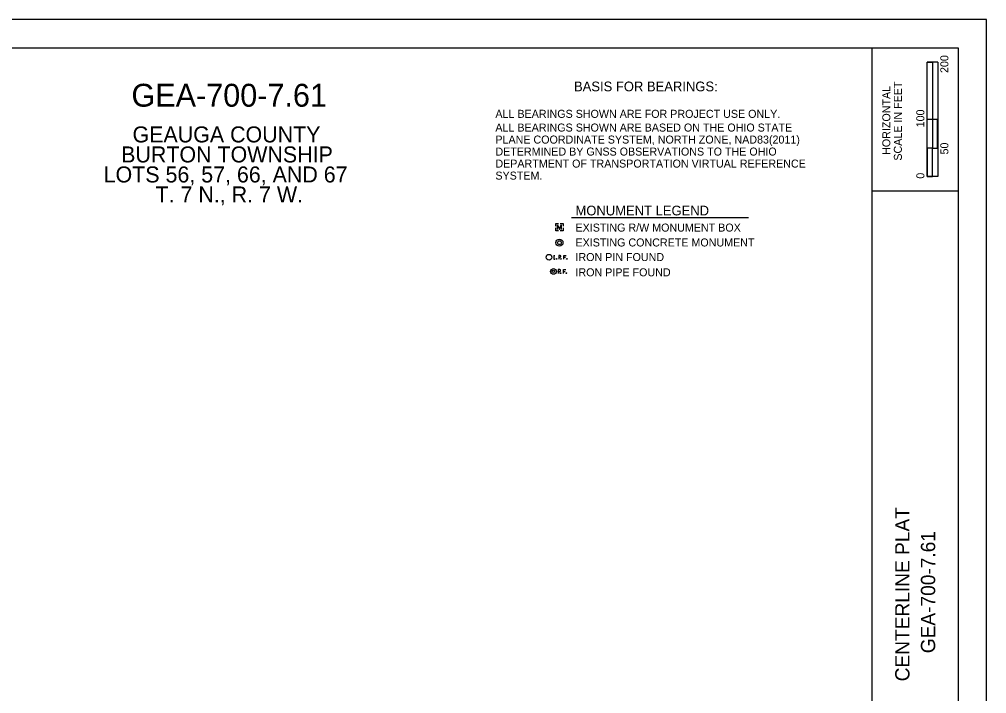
# Model space of a CAD drawing. Extents: x -6.7 to 34, y -1.6 to 22.
# Drawn here: x 17.08 to 34, y 10.21 to 22 of the extents above; entities that cross this region are included whole.
import ezdxf

# ---------------------------------------------------------------- set-up
doc = ezdxf.new("R2010")
doc.units = 0
for name, color, linetype in [('SH_Border', 7, 'Continuous'), ('SH_Cut_Line', 7, 'Continuous'), ('SH_Named_Boundary', 7, 'Continuous'), ('SH_Text', 7, 'Continuous')]:
    doc.layers.add(name, color=color, linetype=linetype)

msp = doc.modelspace()

# ---------------------------------------------------------------- linework, layer by layer
at = {"layer": 'SH_Border'}
for p, q in [((32, 0.5), (32, 21.5)), ((32, 19), (33.5, 19))]:
    msp.add_line(p, q, dxfattribs=at)
msp.add_lwpolyline([(1.5, 21.5), (33.5, 21.5), (33.5, 0.5), (1.5, 0.5)], close=True, dxfattribs=at)
at = {"layer": 'SH_Cut_Line'}
for p, q in [((32.957, 19.25), (32.957, 21.25)), ((33.144, 21.25), (32.957, 21.25)), ((32.957, 20.25), (32.957, 21.25)), ((32.957, 21.25), (33.05, 21.25)), ((33.05, 21.25), (33.051, 21.25)), ((33.051, 21.25), (33.051, 20.25)), ((33.144, 21.25), (33.144, 19.25)), ((33.051, 20.25), (32.957, 20.25)), ((33.143, 20.25), (33.05, 20.25)), ((33.05, 20.25), (33.05, 19.75)), ((33.143, 19.75), (33.143, 20.25)), ((33.05, 19.75), (32.957, 19.75)), ((32.957, 19.75), (32.957, 19.25)), ((33.05, 19.25), (33.05, 19.75)), ((33.05, 19.75), (33.143, 19.75)), ((33.144, 19.25), (32.957, 19.25)), ((32.957, 19.25), (33.05, 19.25))]:
    msp.add_line(p, q, dxfattribs=at)
at = {"layer": 'SH_Named_Boundary'}
msp.add_lwpolyline([(0, 0), (34, 0), (34, 22), (0, 22)], close=True, dxfattribs=at)
at = {"layer": 'SH_Text'}
for p, q in [((26.739, 18.534), (29.832, 18.534)), ((26.527, 18.368), (26.527, 18.368)), ((26.429, 17.873), (26.445, 17.873)), ((26.429, 17.873), (26.445, 17.873)), ((26.429, 17.806), (26.445, 17.806)), ((26.437, 17.806), (26.437, 17.873)), ((26.514, 17.841), (26.54, 17.841)), ((26.607, 17.806), (26.607, 17.873)), ((26.607, 17.873), (26.646, 17.873)), ((26.607, 17.841), (26.635, 17.841)), ((26.6, 17.559), (26.6, 17.625)), ((26.6, 17.625), (26.638, 17.625)), ((26.506, 17.593), (26.533, 17.593)), ((26.6, 17.593), (26.627, 17.593))]:
    msp.add_line(p, q, dxfattribs=at)
for points in [[(26.465, 18.383), (26.465, 18.43), (26.512, 18.43)], [(26.512, 18.305), (26.465, 18.305), (26.465, 18.352)], [(26.496, 18.326), (26.496, 18.409), (26.527, 18.326), (26.558, 18.409), (26.558, 18.326)], [(26.542, 18.43), (26.59, 18.43), (26.59, 18.383)], [(26.59, 18.352), (26.59, 18.305), (26.542, 18.305)], [(26.54, 17.873), (26.514, 17.873), (26.514, 17.806)], [(26.533, 17.625), (26.506, 17.625), (26.506, 17.559)]]:
    msp.add_lwpolyline(points, dxfattribs=at)
for centre, radius in [((26.527, 18.095), 0.0625), ((26.527, 18.095), 0.0333), ((26.345, 17.84), 0.05), ((26.477, 17.811), 0.00583), ((26.554, 17.811), 0.00583), ((26.656, 17.811), 0.00583), ((26.423, 17.592), 0.05), ((26.423, 17.592), 0.0206), ((26.547, 17.563), 0.00583), ((26.648, 17.563), 0.00583)]:
    msp.add_circle(centre, radius, dxfattribs=at)
for centre in [(26.538, 17.857), (26.531, 17.609)]:
    msp.add_arc(centre, 0.0162, 278.8803, 81.1197, dxfattribs=at)

# ---------------------------------------------------------------- texts
at = {"layer": 'SH_Cut_Line'}
for s, height, p in [('200', 0.14, (33.33, 21.062)), ('HORIZONTAL', 0.14, (32.315, 19.63)), ('SCALE IN FEET', 0.14, (32.517, 19.529)), ('100', 0.14, (32.91, 20.112)), ('50', 0.14, (33.33, 19.637)), ('0', 0.14, (32.91, 19.214)), ('CENTERLINE PLAT', 0.25, (32.65, 10.425)), ('GEA-700-7.61', 0.25, (33.1, 10.916))]:
    msp.add_text(s, height=height, rotation=90, dxfattribs=at).set_placement(p)
at = {"layer": 'SH_Text'}
for s, height, p in [('GEA-700-7.61', 0.4, (19.041, 20.473)), ('BASIS FOR BEARINGS:', 0.17, (26.782, 20.742)), ('ALL BEARINGS SHOWN ARE FOR PROJECT USE ONLY.', 0.14, (25.407, 20.278)), ('ALL BEARINGS SHOWN ARE BASED ON THE OHIO STATE', 0.14, (25.407, 20.038)), ('GEAUGA COUNTY', 0.28, (19.06, 19.848)), ('PLANE COORDINATE SYSTEM, NORTH ZONE, NAD83(2011)', 0.14, (25.407, 19.828)), ('BURTON TOWNSHIP', 0.28, (18.861, 19.498)), ('DETERMINED BY GNSS OBSERVATIONS TO THE OHIO', 0.14, (25.407, 19.618)), ('DEPARTMENT OF TRANSPORTATION VIRTUAL REFERENCE', 0.14, (25.407, 19.408)), ('LOTS 56, 57, 66, AND 67', 0.28, (18.555, 19.148)), ('SYSTEM.', 0.14, (25.407, 19.198)), ('T. 7 N., R. 7 W.', 0.28, (19.463, 18.798)), ('MONUMENT LEGEND', 0.17, (26.808, 18.572)), ('EXISTING R/W MONUMENT BOX', 0.14, (26.808, 18.289)), ('EXISTING CONCRETE MONUMENT', 0.14, (26.808, 18.029)), ('IRON PIN FOUND', 0.14, (26.808, 17.774)), ('IRON PIPE FOUND', 0.14, (26.808, 17.507))]:
    msp.add_text(s, height=height, dxfattribs=at).set_placement(p)

doc.saveas('drawing.dxf')
